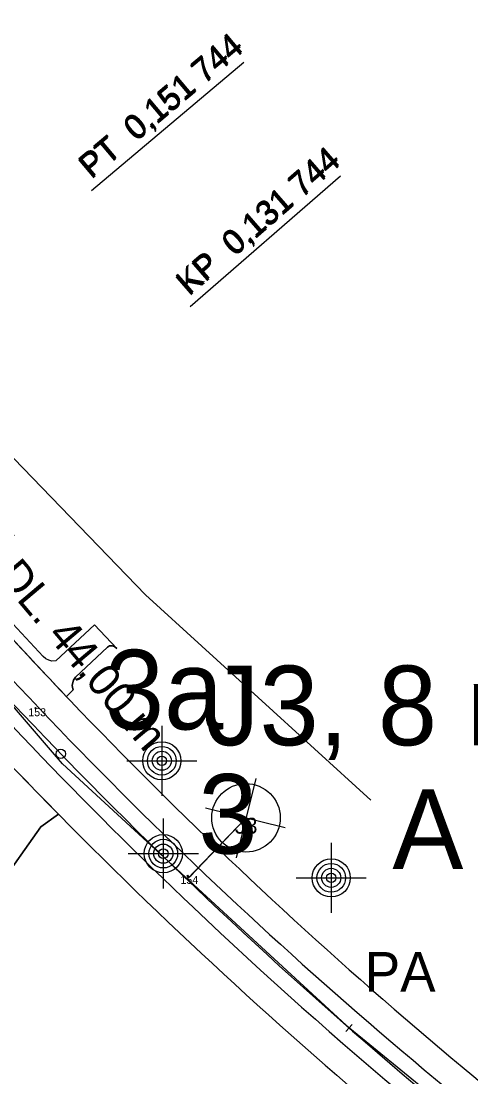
# Model space of a CAD drawing. Extents: x -606444 to -604546, y -1158114 to -1156869.
# Drawn here: x -605014.7 to -604958.2, y -1157503.1 to -1157370.5 of the extents above; entities that cross this region are included whole.
import ezdxf

# ---------------------------------------------------------------- set-up
doc = ezdxf.new("R2010")
doc.units = 0
for name, color, linetype in [('0_sondy', 7, 'Continuous'), ('B_TRAM', 7, 'Continuous'), ('B_ZELEN', 7, 'Continuous'), ('geofyzikální profily_předběžný GTP', 7, 'Continuous'), ('GF řezy', 7, 'Continuous'), ('jádrové vrty_předběžný GTP', 7, 'Continuous'), ('netisk', 7, 'Continuous'), ('netisk2', 7, 'Continuous'), ('NS_VB', 7, 'Continuous'), ('NS_VB_POP', 7, 'Continuous'), ('OSA', 7, 'Continuous'), ('OSAPOP', 7, 'Continuous'), ('podélný profil trasou tramvaje', 7, 'Continuous'), ('Sondy 2', 7, 'Continuous'), ('sondy současného průzkumu', 7, 'Continuous')]:
    doc.layers.add(name, color=color, linetype=linetype)

# ---------------------------------------------------------------- blocks, each defined once
blk = doc.blocks.new('709')
for p, q in [((0, 2.2), (0, -2.2)), ((-2.2, 0), (2.2, 0))]:
    blk.add_line(p, q)
for radius in [1.2, 0.9, 0.6, 0.3]:
    blk.add_circle((0, 0), radius)
blk = doc.blocks.new('IG vrt podr')
at = {"layer": 'sondy současného průzkumu'}
for p, q in [((0.412, 1.649), (-0.418, -1.672)), ((-1.698, 0.422), (1.644, -0.408))]:
    blk.add_line(p, q, dxfattribs=at)
blk.add_circle((-0.002, 0.001), 1.434, dxfattribs=at)

msp = doc.modelspace()

# ---------------------------------------------------------------- linework, layer by layer
for p, q in [((-605012.91, -1157456.81), (-605013.01, -1157456.71)), ((-605012.91, -1157456.81), (-605013.01, -1157456.91)), ((-605012.91, -1157456.81), (-605012.81, -1157456.71)), ((-605012.91, -1157456.81), (-605012.81, -1157456.91)), ((-604986.46, -1157470.58), (-604986.56, -1157470.48)), ((-604986.46, -1157470.58), (-604986.56, -1157470.68)), ((-604986.46, -1157470.58), (-604986.36, -1157470.48)), ((-604986.46, -1157470.58), (-604986.36, -1157470.68)), ((-604993.8, -1157477.88), (-604993.9, -1157477.78)), ((-604993.8, -1157477.88), (-604993.9, -1157477.98)), ((-604993.8, -1157477.88), (-604993.7, -1157477.78)), ((-604993.8, -1157477.88), (-604993.7, -1157477.98))]:
    msp.add_line(p, q)
at = {"layer": 'B_TRAM'}
for radius in [594.5, 605.5]:
    msp.add_arc((-604578.51, -1157045.35), radius, 222.04255, 233.60158, dxfattribs=at)
at = {"layer": 'B_ZELEN'}
for p, q in [((-605012.23, -1157471.69), (-605010, -1157470.13)), ((-605017.61, -1157479.23), (-605012.23, -1157471.69))]:
    msp.add_line(p, q, dxfattribs=at)
for points in [[(-605003.88, -1157449.12), (-605003.59, -1157448.97), (-605003.24, -1157448.95), (-605002.92, -1157449.08), (-605002.67, -1157449.29), (-605005.49, -1157446.33), (-605010.36, -1157450.85), (-605010.84, -1157450.88), (-605011.22, -1157450.78), (-605011.6, -1157450.58), (-605011.93, -1157450.29), (-605017.42, -1157444.44), (-605017.72, -1157443.76), (-605017.79, -1157443.02), (-605017.76, -1157442.43), (-605017.62, -1157441.89), (-605017.39, -1157441.35), (-605017.01, -1157440.74), (-605016.51, -1157440.08), (-605019.15, -1157442.7), (-605020.01, -1157443.47)], [(-605009.03, -1157455.32), (-605008.16, -1157454.49), (-605008.26, -1157454.19), (-605008.3, -1157453.92), (-605008.15, -1157453.28), (-605007.87, -1157452.9), (-605003.88, -1157449.12)]]:
    msp.add_lwpolyline(points, dxfattribs=at)
for radius, end in [(594.5, 223.59935), (605.5, 224.55107)]:
    msp.add_arc((-604578.51, -1157045.35), radius, 222.04255, end, dxfattribs=at)
at = {"layer": 'geofyzikální profily_předběžný GTP'}
msp.add_lwpolyline([(-605670.78, -1157141.05), (-605656.02, -1157139.47), (-605613.88, -1157139.36), (-605584.8, -1157137.32), (-605531.41, -1157136.33), (-605491.56, -1157133.4), (-605482.07, -1157135.61), (-605438.78, -1157126.66), (-605383.23, -1157124.52), (-605352.34, -1157123.33), (-605321.95, -1157126), (-605284.14, -1157130.42), (-605243.3, -1157142.6), (-605207.83, -1157158.83), (-605179.98, -1157186.15), (-605165.29, -1157202.67), (-605149.23, -1157223.34), (-605135.07, -1157244.47), (-605115.92, -1157286.28), (-605103.22, -1157315.84), (-605095.33, -1157330.32), (-605036.97, -1157403.36), (-604999.08, -1157442.54), (-604970.8, -1157468.35)], dxfattribs=at)
at = {"layer": 'netisk'}
msp.add_line((-604993.56, -1157478.04), (-604986.46, -1157470.58), dxfattribs=at)
at = {"layer": 'netisk2'}
msp.add_line((-604986.46, -1157470.58), (-604993.88, -1157478.32), dxfattribs=at)
at = {"layer": 'NS_VB'}
for p, q in [((-605011.93, -1157450.29), (-605017.42, -1157444.44)), ((-605005.49, -1157446.33), (-605010.36, -1157450.85)), ((-605005.49, -1157446.33), (-605002.67, -1157449.29)), ((-605003.88, -1157449.12), (-605007.87, -1157452.9)), ((-605003.59, -1157448.97), (-605003.88, -1157449.12)), ((-605003.24, -1157448.95), (-605003.59, -1157448.97)), ((-605002.92, -1157449.08), (-605003.24, -1157448.95)), ((-605002.67, -1157449.29), (-605002.92, -1157449.08)), ((-605011.6, -1157450.58), (-605011.93, -1157450.29)), ((-605011.22, -1157450.78), (-605011.6, -1157450.58)), ((-605010.84, -1157450.88), (-605011.22, -1157450.78)), ((-605010.36, -1157450.85), (-605010.84, -1157450.88)), ((-605007.87, -1157452.9), (-605008.15, -1157453.28)), ((-605008.15, -1157453.28), (-605008.3, -1157453.92)), ((-605008.3, -1157453.92), (-605008.26, -1157454.19)), ((-605008.26, -1157454.19), (-605008.16, -1157454.49)), ((-605008.16, -1157454.49), (-605009.03, -1157455.32)), ((-605010, -1157470.13), (-605012.23, -1157471.69)), ((-605012.23, -1157471.69), (-605017.61, -1157479.23))]:
    msp.add_line(p, q, dxfattribs=at)
for radius in [594.5, 605.5]:
    msp.add_arc((-604578.51, -1157045.35), radius, 222.04255, 233.60156, dxfattribs=at)
at = {"layer": 'OSA'}
for centre, radius, start, end in [((-604578.51, -1157045.35), 600, 221.02098, 233.60156), ((-604578.51, -1157045.35), 602, 221.02094, 226.47692), ((-604591.87, -1157057.41), 580, 222.06105, 233.72643), ((-604593.66, -1157061.3), 580, 226.47692, 233.7757)]:
    msp.add_arc(centre, radius, start, end, dxfattribs=at)
at = {"layer": 'OSAPOP'}
for p, q in [((-605005.88, -1157391.73), (-604986.75, -1157375.64)), ((-604993.47, -1157406.33), (-604974.61, -1157389.92)), ((-604973.91, -1157497.43), (-604973.12, -1157496.53))]:
    msp.add_line(p, q, dxfattribs=at)
msp.add_circle((-605009.73, -1157462.54), 0.6, dxfattribs=at)
at = {"layer": 'podélný profil trasou tramvaje'}
for points in [[(-604973.89, -1157496.65), (-605009.52, -1157463.78), (-605083.89, -1157377.09), (-605085.67, -1157373.96), (-605102.48, -1157348.99)], [(-604973.89, -1157496.65), (-604952.36, -1157514.24), (-604916.22, -1157540.87)]]:
    msp.add_lwpolyline(points, dxfattribs=at)

# ---------------------------------------------------------------- block references
at = {"layer": '0_sondy', "xscale": 2, "yscale": 2}
for p in [(-604996.85, -1157475.08), (-604975.76, -1157478.12)]:
    msp.add_blockref('709', p, dxfattribs=at)
at = {"layer": 'jádrové vrty_předběžný GTP', "xscale": 3, "yscale": 3}
msp.add_blockref('IG vrt podr', (-604986.46, -1157470.58), dxfattribs=at)
at = {"layer": 'Sondy 2', "xscale": 2, "yscale": 2}
msp.add_blockref('709', (-604997.04, -1157463.41), dxfattribs=at)

# ---------------------------------------------------------------- texts
for s, height, p in [('153', 1, (-605013.81, -1157457.81)), ('J3', 2, (-604987.85, -1157472.57)), ('154', 1, (-604994.7, -1157478.88))]:
    msp.add_text(s, height=height).set_placement(p)
at = {"layer": '0_sondy'}
msp.add_text('3', height=10, dxfattribs=at).set_placement((-604992.45, -1157475.08))
at = {"layer": 'geofyzikální profily_předběžný GTP'}
msp.add_text('A', height=10, dxfattribs=at).set_placement((-604968.08, -1157477.01))
at = {"layer": 'GF řezy'}
msp.add_text('PA', height=5, dxfattribs=at).set_placement((-604971.56, -1157492.44))
at = {"layer": 'jádrové vrty_předběžný GTP'}
msp.add_text('J3, 8 m', height=10, dxfattribs=at).set_placement((-604991.45, -1157461.46))
at = {"layer": 'NS_VB_POP'}
msp.add_text('NÁSTUPIŠTĚ DL. 44,00 m', height=4, rotation=310.0661, dxfattribs=at).set_placement((-605040.44, -1157413.36))
at = {"layer": 'OSAPOP'}
for s, rotation, p in [('PT  0,151 744', 40.0661, (-605005.86, -1157390.21)), ('PT  0,151 744', 40.0661, (-605005.88, -1157390.42)), ('KP  0,131 744', 41.021, (-604993.6, -1157405.12)), ('KP  0,131 744', 41.021, (-604993.58, -1157404.91))]:
    msp.add_text(s, height=3, rotation=rotation, dxfattribs=at).set_placement(p)
at = {"layer": 'Sondy 2'}
msp.add_text('3a', height=10, dxfattribs=at).set_placement((-605004.19, -1157459.47))

doc.saveas('drawing.dxf')
